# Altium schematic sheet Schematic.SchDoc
size A4
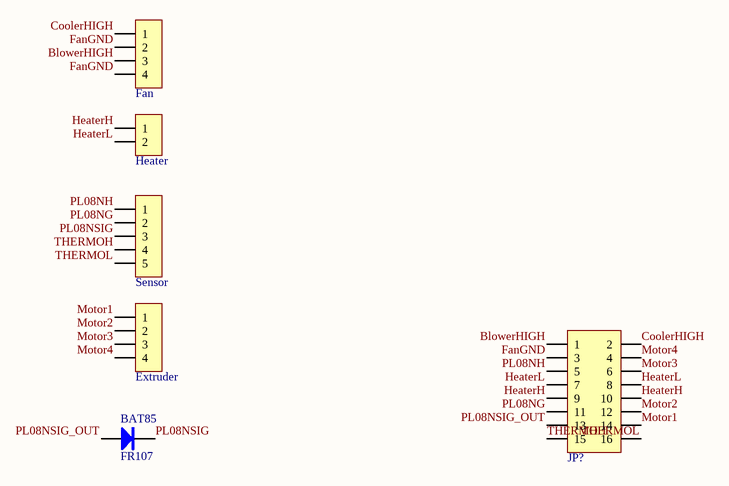
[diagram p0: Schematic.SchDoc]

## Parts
BAT85  FR107  [DO-41]
Extruder  HDR-1X4  [XH2.54-LI-4P]  (value not drawn)
Fan  HDR-1X4  [XH2.54-LI-4P]  (value not drawn)
Heater  HDR-1X2  [KF128-5.08-2P]  (value not drawn)
JP?  Header 8X2  [IDC2.54-LI-2x8P]  (value not drawn)
Sensor  HDR-1X5  [XH2.54-LI-5P]  (value not drawn)

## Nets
BlowerHIGH: Fan.3 JP?.1
CoolerHIGH: Fan.1 JP?.2
FanGND: Fan.2 Fan.4 JP?.3
HeaterH: Heater.1 JP?.9 JP?.10
HeaterL: Heater.2 JP?.7 JP?.8
Motor1: Extruder.1 JP?.14
Motor2: Extruder.2 JP?.12
Motor3: Extruder.3 JP?.6
Motor4: Extruder.4 JP?.4
PL08NG: JP?.11 Sensor.2
PL08NH: JP?.5 Sensor.1
PL08NSIG: BAT85.2(K) Sensor.3
PL08NSIG_OUT: BAT85.1(A) JP?.13
THERMOH: JP?.15 Sensor.4
THERMOL: JP?.16 Sensor.5

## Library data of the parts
BAT85 = FR107: 快恢复整流二极管; BOM名称: 快恢复二极管; 版权归属: 封装库来自淘宝 ID：黄晶宝石; 属性: 700V/1A
Extruder Fan = Header 4: 4P接插件; 版权归属: 封装库来自淘宝 ID：黄晶宝石
Heater = Header 2: 2P接插件; 版权归属: 封装库来自淘宝卖家 ID：黄晶宝石
JP? = Header 8X2: 8*2P接插件; 版权归属: 封装库来自淘宝 ID：黄晶宝石
Sensor = Header 5: 5P接插件; 版权归属: 封装库来自淘宝 ID：黄晶宝石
